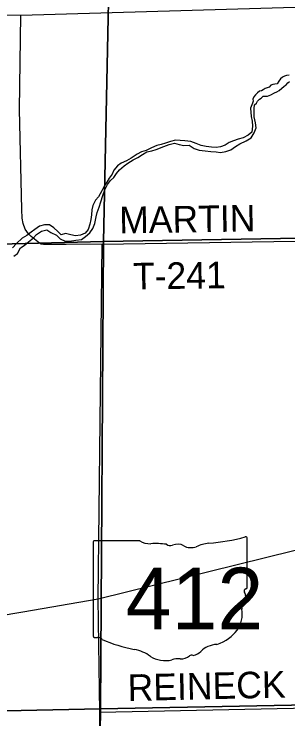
# Model space of a CAD drawing. Extents: x 1588073 to 2013523, y 1090242 to 1357120.
# Drawn here: x 1816219 to 1819310, y 1223082 to 1231039 of the extents above; entities that cross this region are included whole.
import ezdxf

# ---------------------------------------------------------------- set-up
doc = ezdxf.new("R2010")
doc.units = 0
for name, color, linetype in [('GM_X_County_Road', 7, 'Continuous'), ('GM_X_Minor_River', 7, 'Continuous'), ('GM_X_Section', 7, 'Continuous'), ('GM_X_State_Location', 7, 'Continuous'), ('GM_X_State_Route', 7, 'Continuous'), ('GM_X_State_Shield', 7, 'Continuous'), ('GM_X_Township_Road', 7, 'Continuous'), ('GM_X_Township_Road_Text', 7, 'Continuous')]:
    doc.layers.add(name, color=color, linetype=linetype)

msp = doc.modelspace()

# ---------------------------------------------------------------- linework, layer by layer
at = {"layer": 'GM_X_County_Road'}
msp.add_lwpolyline([(1814895.7, 1231041.5), (1816295.9, 1231026.1), (1820037.2, 1231138.2), (1822397.6, 1231176.1), (1822544, 1231159.8), (1822713.9, 1231105.1), (1823174.2, 1231128.5), (1823644.2, 1231133.7), (1823903.7, 1231166.1), (1825222.2, 1231233.3), (1827893.8, 1231262.6)], dxfattribs=at)
at = {"layer": 'GM_X_Minor_River'}
for points in [[(1819326, 1230349.9), (1819295.9, 1230346.2), (1819271.8, 1230338.4), (1819247.7, 1230326.5), (1819227.6, 1230308.6), (1819209.3, 1230282.7), (1819187.1, 1230250.8), (1819163, 1230249), (1819141, 1230245.1), (1819118.9, 1230235.3), (1819098.7, 1230215.4), (1819074.6, 1230205.6), (1819052.5, 1230197.7), (1819032.3, 1230183.8), (1819012.2, 1230174), (1818988.2, 1230168.2), (1818968, 1230152.3), (1818945.8, 1230128.4), (1818925.6, 1230106.5), (1818915.4, 1230078.5), (1818917.2, 1230056.4), (1818909.1, 1230032.4), (1818886.4, 1229975.6)], [(1818929.1, 1229975.3), (1818933, 1230016.1), (1818955.1, 1230032), (1818967.3, 1230056), (1818987.5, 1230079.9), (1819009.6, 1230091.7), (1819031.8, 1230111.6), (1819055.9, 1230113.4), (1819079.9, 1230113.2), (1819116.1, 1230129), (1819158.3, 1230148.7), (1819184.4, 1230162.5), (1819210.6, 1230178.3), (1819269, 1230224), (1819289.2, 1230239.9), (1819307.4, 1230263.8), (1819329.5, 1230279.7)], [(1818886.4, 1229975.6), (1818896.4, 1229881.5), (1818905.1, 1229831.1), (1818911.6, 1229774.8), (1818901.7, 1229706.9), (1818862.8, 1229673.9), (1818803.9, 1229643.4), (1818747.4, 1229626.9), (1818696.9, 1229610.3), (1818648.3, 1229589.6), (1818603.4, 1229558.7), (1818550.9, 1229542.1), (1818500.5, 1229531.5), (1818448.6, 1229536.9), (1818386.8, 1229544.6), (1818331, 1229556.2), (1818273.5, 1229577.8), (1818214.1, 1229601.5), (1818146.2, 1229607.3), (1818092.2, 1229610.8), (1818042.3, 1229614.2), (1817985.9, 1229601.7), (1817929.3, 1229583.2), (1817878.8, 1229568.6), (1817830.4, 1229555.9), (1817769.7, 1229529.5), (1817710.8, 1229499), (1817656.3, 1229482.5), (1817609.5, 1229457.7), (1817542.3, 1229413.4), (1817487.4, 1229382.8), (1817428.6, 1229356.4), (1817387.7, 1229325.4), (1817346.4, 1229278.5), (1817325.1, 1229232.9), (1817291.8, 1229185.7), (1817264.6, 1229142.4), (1817235.4, 1229097.1), (1817209.9, 1229043.6), (1817172, 1228976.5), (1817138.9, 1228937.3), (1817109.4, 1228880), (1817097.9, 1228828.2), (1817094.4, 1228772.1), (1817085.1, 1228722.3), (1817073.6, 1228668.4), (1817056, 1228608.8), (1817020.8, 1228567.6), (1816970.1, 1228545), (1816911.8, 1228536.6), (1816858.1, 1228548.1), (1816800.5, 1228563.7), (1816752, 1228549), (1816713, 1228586.1), (1816668, 1228627.5), (1816618.9, 1228660.9), (1816562.7, 1228658.4), (1816506.3, 1228645.9), (1816453.2, 1228607.3), (1816410.3, 1228576.4), (1816363.4, 1228541.6), (1816308.4, 1228509), (1816246.7, 1228448.6), (1816199.4, 1228401.8)], [(1817220.5, 1228991.2), (1817242.2, 1229054.8), (1817273.9, 1229114.1), (1817307.2, 1229161.2), (1817346.1, 1229194.3), (1817375.4, 1229239.6), (1817410.6, 1229282.7), (1817459.9, 1229327.5), (1817504.7, 1229356.3), (1817561.8, 1229394.8), (1817614.6, 1229421.5), (1817669.5, 1229454), (1817718.3, 1229482.8), (1817772.8, 1229497.3), (1817823.3, 1229512), (1817908.3, 1229545.7), (1817968.9, 1229568.1), (1818029.3, 1229580.5), (1818083, 1229567), (1818136.8, 1229557.5), (1818194.9, 1229557.9), (1818252, 1229520.2), (1818307.5, 1229502.7), (1818377.4, 1229494.7), (1818441.3, 1229489), (1818499.2, 1229483.4), (1818549.2, 1229478), (1818609.4, 1229486.4), (1818664.1, 1229506.9), (1818719.2, 1229545.5), (1818768, 1229574.2), (1818837, 1229608.4), (1818893.9, 1229640.9), (1818929.6, 1229700.1), (1818953.1, 1229753.6), (1818942.6, 1229810), (1818928.5, 1229880.6), (1818929.1, 1229975.3)], [(1816214.8, 1228305.1), (1816255.7, 1228338.1), (1816289.4, 1228399.3), (1816332.3, 1228428.2), (1816381.4, 1228468.9), (1816438.7, 1228513.5), (1816473.7, 1228550.6), (1816526.8, 1228587.2), (1816589.3, 1228603.6), (1816632.5, 1228572.3), (1816697.8, 1228544.4), (1816738.8, 1228503.2), (1816794.1, 1228475.6), (1816846.1, 1228476.2), (1816916.6, 1228488.3), (1816978.8, 1228494.6), (1817025.8, 1228529.4), (1817072.9, 1228570.2), (1817108.3, 1228617.4), (1817131.8, 1228674.9), (1817143.8, 1228748.7), (1817157.3, 1228800.5), (1817180.9, 1228860), (1817198.5, 1228919.6), (1817220.5, 1228991.2)]]:
    msp.add_lwpolyline(points, dxfattribs=at)
at = {"layer": 'GM_X_Section'}
for points in [[(1817336.3, 1233708.2), (1822620.3, 1233829.4), (1822562.1, 1228560.6), (1817226.4, 1228473.5)], [(1812346.7, 1233625.2), (1817336.3, 1233708.2), (1817226.4, 1228473.5), (1812224.6, 1228344.3), (1812227.2, 1228444.3)], [(1822562.1, 1228560.6), (1822489.5, 1223297.9), (1817193.8, 1223196.6), (1817226.4, 1228473.5)], [(1817226.4, 1228473.5), (1817193.8, 1223196.6), (1812172.2, 1223091.5), (1812168.6, 1223159.6), (1812224.6, 1228344.3)], [(1822489.5, 1223297.9), (1822442.8, 1218013.1), (1822250.6, 1218004.3), (1817118.9, 1217888), (1817193.8, 1223196.6)], [(1817193.8, 1223196.6), (1817118.9, 1217888), (1816936.8, 1217887.1), (1812121.6, 1217818.8), (1812172.2, 1223091.5)]]:
    msp.add_lwpolyline(points, close=True, dxfattribs=at)
at = {"layer": 'GM_X_State_Route'}
for points in [[(1816296.7, 1224288), (1816316.9, 1224291.5), (1817169.3, 1224436.5), (1822516.9, 1225760.4), (1822621.7, 1225783.2), (1825187, 1226081.6), (1826951, 1226321.1), (1827701.4, 1226417.4)], [(1814910.8, 1224052.3), (1814912.7, 1224052.6), (1816296.7, 1224288)]]:
    msp.add_lwpolyline(points, dxfattribs=at)
at = {"layer": 'GM_X_State_Shield'}
for p, q in [((1818850.3, 1224567), (1818850.3, 1225119.8)), ((1817110.1, 1225075.4), (1817110.1, 1224018.8)), ((1817636.8, 1225093.6), (1817127.2, 1225093.6)), ((1818850.1, 1224567.2), (1818850.3, 1224567))]:
    msp.add_line(p, q, dxfattribs=at)
for centre, major_axis, start_param, end_param in [((1818230.4, 1226534.1), (1845.5, 0), 4.814394, 5.042369), ((1818831, 1225122.1), (19.4, 0), 6.141152, 7.989035), ((1817130, 1225077.7), (20.2, 0), 1.712693, 3.28349), ((1817758.2, 1225216.3), (195.5, 0), 4.042523, 4.731795), ((1817823, 1224500.4), (702, 0), 1.404758, 1.657858), ((1817982.4, 1225083.1), (56.4, 0), 3.836095, 5.185415), ((1818065.2, 1224961), (117.3, 0), 0.950623, 2.079405), ((1818216.6, 1225128.5), (141.1, 0), 4.081561, 5.145723), ((1818465.8, 1224770.9), (371.3, 0), 1.699011, 2.107814), ((1818829.6, 1224564.9), (20.7, 0), 5.05454, 6.418171), ((1818845.8, 1224526.5), (30, 0), 1.883978, 3.671073), ((1818655.1, 1224456.6), (180, 0), 5.934695, 6.695948), ((1818919.7, 1224335.7), (130.9, 0), 2.387724, 3.262537), ((1818333.8, 1224265.4), (461.6, 0), 5.101752, 6.440018), ((1817130.2, 1224016.5), (20.3, 0), 3.00124, 4.508301), ((1817133.3, 1224124.6), (155.2, 0), 4.665946, 4.897461), ((1817165, 1223957.8), (56, 0), 0.519207, 1.627899), ((1817871.6, 1224907.2), (1332.7, 0), 4.195997, 4.488961), ((1818528.4, 1223722.1), (252.8, 0), 1.647645, 2.488434), ((1817474.3, 1223544.1), (417, 0), 0.823519, 1.323587), ((1818208.1, 1223916.4), (149.1, 0), 4.937069, 5.64225), ((1817925.3, 1223952.6), (264.6, 0), 4.026481, 4.996735), ((1818097.5, 1223873.4), (141, 0), 4.691044, 5.507374), ((1818225, 1223771.1), (39.7, 0), 1.147584, 2.315152), ((1818078.2, 1223587.3), (217.4, 0), 1.495662, 1.94098)]:
    msp.add_ellipse(centre, major_axis=major_axis, ratio=0.8, start_param=start_param, end_param=end_param, dxfattribs=at)
at = {"layer": 'GM_X_Township_Road'}
for points in [[(1817121.9, 1217871.3), (1817186.8, 1223159.3), (1817169.3, 1224436.5), (1817213.5, 1228442.1), (1816808.5, 1228438.5), (1816551.9, 1228438.7), (1816522.8, 1228442.2), (1816504.3, 1228454), (1816466.4, 1228482.2), (1816412.7, 1228528.1), (1816383, 1228559.1), (1816345.3, 1228609.7), (1816320.5, 1228674.7), (1816309.4, 1228735.2), (1816305.7, 1228831.7), (1816281.7, 1229963.4), (1816295.9, 1231026.1)], [(1817213.5, 1228442.1), (1822539.1, 1228523.1), (1825203.8, 1228550.8), (1827886.1, 1228597.8)], [(1817186.8, 1223159.3), (1822466.8, 1223269.1)]]:
    msp.add_lwpolyline(points, dxfattribs=at)

# ---------------------------------------------------------------- texts
at = {"layer": 'GM_X_State_Location'}
msp.add_text('412', height=1, rotation=0.00001, dxfattribs=at).set_placement((1817607.6, 1224404.1))
for s in ['s', 'r']:
    msp.add_text(s, height=1, dxfattribs=at).set_placement((1817960.6, 1224476.9))
at = {"layer": 'GM_X_State_Shield'}
msp.add_text('412', height=696.1, dxfattribs=at).set_placement((1817479.1, 1224093.3))
at = {"layer": 'GM_X_Township_Road_Text'}
for s, rotation, p in [('MARTIN', 0.87088, (1817407.8, 1228563.1)), ('T-241', 0.84312, (1817562.4, 1227929.9)), ('REINECK', 1.26971, (1817503.8, 1223284.2))]:
    msp.add_text(s, height=300, rotation=rotation, dxfattribs=at).set_placement(p)

doc.saveas('drawing.dxf')
